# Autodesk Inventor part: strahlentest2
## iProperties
Created: 2005-05
Part Number: strahlentest2
Document SubType Name: Modeling
Designer: Nordmeyer
Manufacturer: Standard
Standards Organization: Custom
Übersetzungsnorm: IGES 5.3
Dateiname: S:\gloria\DM\Strahlengang\alte files\gloria-bwd_Linsen-test2.IGS
Vorprozessor: HarmonyWare Translators
Postprozessor: Build: 147, Release: 9 SP2 - Date: Thu 12/16/2004
Gesendete Einheiten: MM
Unbestimmtheit: 0.0001
Author: Nordmeyer
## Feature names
1. Sweeping2
2. Sweeping3
3. Sweeping4
